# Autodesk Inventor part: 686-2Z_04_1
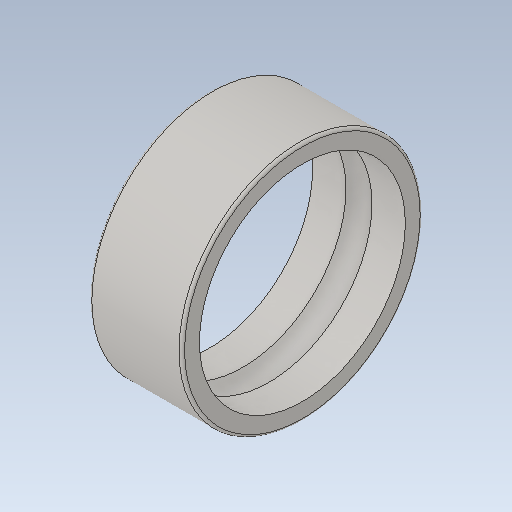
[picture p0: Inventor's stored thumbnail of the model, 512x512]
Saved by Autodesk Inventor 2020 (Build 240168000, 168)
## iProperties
Created: 2017-11
Part Number: 686-2Z_04_1
Material: Ogólny
Document SubType Name: Modeling
Designer: Tomasz
Density: 1 g/cm^3
Appearance: Domyślna
Sending System: SolidWorks 2017
Last Author: Tomasz
Last Saved: 2017-11-19
Source: 686-2Z_04_1
Author: Tomasz
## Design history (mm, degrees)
feature "Imported1"
node "Bryła1"
